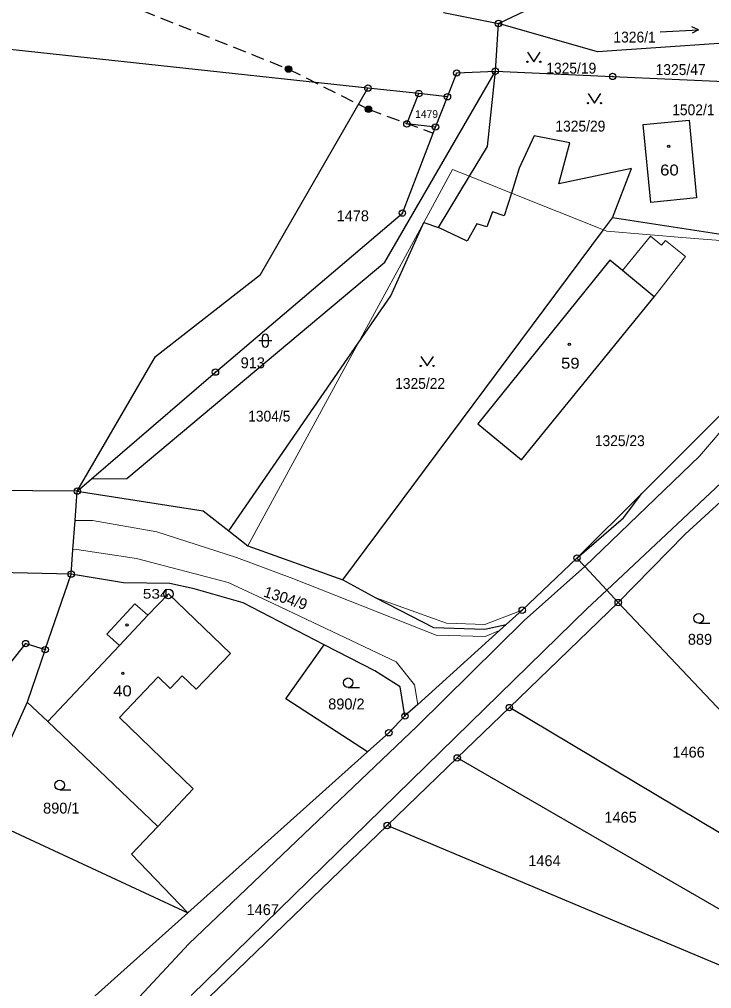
# Model space of a CAD drawing. Extents: x -872229 to -869198, y -1075981 to -1074329.
# Drawn here: x -871207 to -871098.8, y -1075369.5 to -1075218 of the extents above; entities that cross this region are included whole.
import ezdxf
from ezdxf.enums import TextEntityAlignment as Align

# ---------------------------------------------------------------- set-up
doc = ezdxf.new("R2010")
doc.units = 0
doc.header["$LTSCALE"] = 0.68
doc.linetypes.add('MEDIUM_DASHED', pattern=[4.5, 3, -1.5])
for name, color, linetype, lineweight in [('1', 7, 'Continuous', 25), ('3', 7, 'Continuous', 25), ('4', 7, 'Continuous', 13), ('5', 7, 'Continuous', 25), ('6', 7, 'Continuous', 25), ('8', 7, 'Continuous', 25)]:
    doc.layers.add(name, color=color, linetype=linetype, lineweight=lineweight)
doc.layers.add('2', color=7, linetype='Continuous')

msp = doc.modelspace()

# ---------------------------------------------------------------- linework, layer by layer
at = {"layer": '1'}
for p, q in [((-871144.59, -1075229.61), (-871152.53, -1075228.75)), ((-871083.47, -1075253.75), (-871114.29, -1075249)), ((-871197.94, -1075291.72), (-871195.74, -1075289.82)), ((-871156.43, -1075305.59), (-871151.31, -1075308.38)), ((-871113.42, -1075309.13), (-871130.43, -1075325.54)), ((-871202.96, -1075316.49), (-871205.8, -1075324.68)), ((-871130.43, -1075325.54), (-871138.58, -1075333.41)), ((-871149.52, -1075343.97), (-871178.79, -1075372.22)), ((-871078.37, -1075373.89), (-871149.52, -1075343.97))]:
    msp.add_line(p, q, dxfattribs=at)
for points in [[(-871152.53, -1075228.75), (-871324.15, -1075210.15), (-871498.95, -1075191.88), (-871564.6, -1075180.17), (-871590.36, -1075167.06), (-871608.79, -1075266.42)], [(-871140.73, -1075216.95), (-871132.14, -1075218.66), (-871123.91, -1075214.69)], [(-871140.11, -1075230.1), (-871138.66, -1075226.39), (-871132.62, -1075226.11), (-871132.14, -1075218.66)], [(-871093.1, -1075221.48), (-871116.67, -1075223.11), (-871132.14, -1075218.66)], [(-871195.74, -1075289.82), (-871190.23, -1075289.74), (-871149.91, -1075255.96), (-871132.62, -1075226.11)], [(-871141.5, -1075250.52), (-871136.68, -1075242.53), (-871133.87, -1075237.87), (-871132.62, -1075226.11)], [(-871132.62, -1075226.11), (-871114.29, -1075226.93), (-871095.65, -1075227.79), (-871094.24, -1075242.63), (-871087.01, -1075243.79), (-871083.47, -1075253.75), (-871081.37, -1075254)], [(-871197.94, -1075291.72), (-871185.72, -1075270.67), (-871169.32, -1075257.9), (-871152.53, -1075228.75)], [(-871141.97, -1075234.83), (-871146.44, -1075234.35), (-871144.59, -1075229.61)], [(-871141.97, -1075234.83), (-871140.11, -1075230.1), (-871144.59, -1075229.61)], [(-871195.74, -1075289.82), (-871176.36, -1075273.13), (-871147.15, -1075248.28), (-871142.34, -1075235.78), (-871141.97, -1075234.83)], [(-871114.29, -1075249), (-871111.33, -1075241.33), (-871122.72, -1075243.71), (-871120.98, -1075237.29), (-871126.58, -1075236.21), (-871128.88, -1075241.26), (-871130.08, -1075245.17), (-871131.22, -1075248.69), (-871133.07, -1075248.06), (-871133.96, -1075250.43), (-871135.52, -1075249.95), (-871137.04, -1075252.66), (-871141.5, -1075250.52)], [(-871174.28, -1075297.93), (-871154.05, -1075268.6), (-871148.96, -1075261.22), (-871143.79, -1075249.74), (-871141.5, -1075250.52)], [(-871156.43, -1075305.59), (-871115.7, -1075250.9), (-871114.29, -1075249)], [(-871119.87, -1075302.18), (-871112.61, -1075295.91), (-871109.75, -1075292.07), (-871095.22, -1075277.55), (-871091.41, -1075272.82)], [(-871197.94, -1075291.72), (-871226.01, -1075291.51), (-871257.41, -1075294.08), (-871286.96, -1075298.91), (-871317.28, -1075305.51), (-871377.38, -1075316.93)], [(-871198.89, -1075304.69), (-871198.62, -1075300.91), (-871198.28, -1075296.29), (-871197.94, -1075291.72)], [(-871197.94, -1075291.72), (-871178.28, -1075294.81), (-871174.28, -1075297.93)], [(-871096.84, -1075292.82), (-871102.97, -1075298.45), (-871113.42, -1075309.13)], [(-871174.28, -1075297.93), (-871171.28, -1075300.27), (-871156.43, -1075305.59)], [(-871119.87, -1075302.18), (-871128.42, -1075310.32), (-871130.92, -1075312.57)], [(-871113.42, -1075309.13), (-871115.21, -1075307.2), (-871118.65, -1075303.5), (-871119.87, -1075302.18)], [(-871198.89, -1075304.69), (-871226.19, -1075304.09), (-871258.51, -1075307.55), (-871284.79, -1075311.01), (-871308.94, -1075316.35)], [(-871243.8, -1075363.33), (-871206.01, -1075315.54), (-871202.96, -1075316.49), (-871198.89, -1075304.69)], [(-871159.38, -1075315.72), (-871172.04, -1075309.18), (-871179.69, -1075306.97), (-871183.47, -1075306.17), (-871190.75, -1075306.03), (-871198.89, -1075304.69)], [(-871151.31, -1075308.38), (-871142.29, -1075313.05), (-871134.29, -1075313.31), (-871130.92, -1075312.57)], [(-871073.44, -1075344.48), (-871095.32, -1075328.3), (-871113.42, -1075309.13)], [(-871130.92, -1075312.57), (-871131.97, -1075313.52), (-871144.74, -1075325.04), (-871146.74, -1075326.85)], [(-871152.59, -1075332.45), (-871165.34, -1075324.15), (-871159.38, -1075315.72)], [(-871146.74, -1075326.85), (-871147.48, -1075322.31), (-871151.47, -1075319.8), (-871159.38, -1075315.72)], [(-871205.8, -1075324.68), (-871208.57, -1075330.98), (-871218.91, -1075339.87), (-871180.67, -1075357.59)], [(-871205.8, -1075324.68), (-871202.55, -1075327.7), (-871185.37, -1075344.12), (-871189.49, -1075348.43), (-871180.67, -1075357.59)], [(-871074.84, -1075352.78), (-871079.33, -1075352.72), (-871094.35, -1075347.04), (-871130.43, -1075325.54)], [(-871146.74, -1075326.85), (-871149.26, -1075329.47), (-871152.59, -1075332.45), (-871180.67, -1075357.59), (-871200.62, -1075375.46)], [(-871077.5, -1075368.64), (-871138.58, -1075333.41), (-871149.52, -1075343.97)]]:
    msp.add_lwpolyline(points, dxfattribs=at)
for points in [[(-871101.2, -1075245.89), (-871108.3, -1075246.6), (-871109.5, -1075234.44), (-871102.34, -1075233.74)], [(-871114.73, -1075255.63), (-871135.35, -1075281.2), (-871128.52, -1075286.81), (-871107.81, -1075261.35), (-871112.73, -1075257.25)]]:
    msp.add_lwpolyline(points, close=True, dxfattribs=at)
at = {"layer": '3'}
for p, q in [((-871100.897, -1075219.631), (-871101.846, -1075220.183)), ((-871169.571, -1075268.211), (-871167.569, -1075268.211)), ((-871169.071, -1075267.711), (-871169.071, -1075268.712)), ((-871168.069, -1075268.712), (-871168.069, -1075267.711)), ((-871100.843, -1075312.36), (-871099.093, -1075312.36)), ((-871155.623, -1075322.42), (-871153.873, -1075322.42)), ((-871200.693, -1075338.4), (-871198.943, -1075338.4))]:
    msp.add_line(p, q, dxfattribs=at)
for points in [[(-871106.888, -1075219.945), (-871100.897, -1075219.631), (-871101.899, -1075219.181)], [(-871127.61, -1075223.129), (-871126.61, -1075224.63), (-871125.61, -1075223.129)], [(-871118.13, -1075229.609), (-871117.13, -1075231.11), (-871116.13, -1075229.609)], [(-871144.28, -1075270.669), (-871143.28, -1075272.17), (-871142.28, -1075270.669)]]:
    msp.add_lwpolyline(points, dxfattribs=at)
for centre, radius in [((-871127.61, -1075224.6295), 0.1), ((-871125.61, -1075224.6295), 0.1), ((-871118.13, -1075231.1095), 0.1), ((-871116.13, -1075231.1095), 0.1), ((-871144.28, -1075272.1695), 0.1), ((-871142.28, -1075272.1695), 0.1), ((-871100.8429, -1075311.6098), 0.75), ((-871155.6229, -1075321.6698), 0.75), ((-871200.6929, -1075337.6498), 0.75)]:
    msp.add_circle(centre, radius, dxfattribs=at)
for centre, start, end in [((-871168.57, -1075267.7109), 0, 180), ((-871168.57, -1075268.7109), 180, 359.98789)]:
    msp.add_arc(centre, 0.5, start, end, dxfattribs=at)
at = {"layer": '4'}
for p, q in [((-871143.79, -1075249.74), (-871139.3, -1075241.49)), ((-871130.08, -1075245.17), (-871115.7, -1075250.9)), ((-871154.05, -1075268.6), (-871143.79, -1075249.74)), ((-871112.73, -1075257.25), (-871108.4, -1075251.89)), ((-871108.4, -1075251.89), (-871106.66, -1075253.29)), ((-871102.8, -1075252.13), (-871083.47, -1075253.75)), ((-871107.81, -1075261.35), (-871102.92, -1075255.07)), ((-871171.28, -1075300.27), (-871154.05, -1075268.6)), ((-871100.71, -1075286.26), (-871088.11, -1075271.44)), ((-871118.65, -1075303.5), (-871100.71, -1075286.26)), ((-871115.21, -1075307.2), (-871096.49, -1075289.67)), ((-871119.87, -1075302.18), (-871109.75, -1075292.07)), ((-871198.28, -1075296.29), (-871195.57, -1075296.31)), ((-871195.57, -1075296.31), (-871185.5, -1075298.06)), ((-871185.5, -1075298.06), (-871173.09, -1075302.09)), ((-871198.62, -1075300.91), (-871198.04, -1075300.83)), ((-871198.04, -1075300.83), (-871188.7, -1075302.25)), ((-871188.7, -1075302.25), (-871174.37, -1075306)), ((-871173.09, -1075302.09), (-871164.26, -1075305.38)), ((-871118.65, -1075303.5), (-871128.14, -1075311.92)), ((-871174.37, -1075306), (-871168.13, -1075308.89)), ((-871164.26, -1075305.38), (-871141.89, -1075314.23)), ((-871118.25, -1075310.04), (-871115.21, -1075307.2)), ((-871186.94, -1075311.08), (-871183.69, -1075307.78)), ((-871183.69, -1075307.78), (-871174, -1075317.1)), ((-871168.13, -1075308.89), (-871148.13, -1075318.4)), ((-871151.31, -1075308.38), (-871140.23, -1075312.34)), ((-871193.35, -1075314.06), (-871188.96, -1075309.34)), ((-871188.96, -1075309.34), (-871186.94, -1075311.08)), ((-871180.16, -1075370.54), (-871118.25, -1075310.04)), ((-871134.25, -1075312.54), (-871128.42, -1075310.32)), ((-871191.36, -1075315.85), (-871186.94, -1075311.08)), ((-871128.14, -1075311.92), (-871144.78, -1075328.38)), ((-871140.23, -1075312.34), (-871134.25, -1075312.54)), ((-871134.21, -1075314.46), (-871131.97, -1075313.52)), ((-871193.35, -1075314.06), (-871191.36, -1075315.85)), ((-871141.89, -1075314.23), (-871134.21, -1075314.46)), ((-871202.55, -1075327.7), (-871191.36, -1075315.85)), ((-871191.36, -1075327.09), (-871185.32, -1075320.73)), ((-871185.32, -1075320.73), (-871183.41, -1075322.55)), ((-871191.36, -1075327.09), (-871179.85, -1075338.26)), ((-871185.37, -1075344.12), (-871179.85, -1075338.26))]:
    msp.add_line(p, q, dxfattribs=at)
for points in [[(-871139.3, -1075241.49), (-871136.68, -1075242.53), (-871130.08, -1075245.17)], [(-871115.7, -1075250.9), (-871115.22, -1075251.09), (-871102.8, -1075252.13)], [(-871106.66, -1075253.29), (-871106.05, -1075252.54), (-871102.92, -1075255.07)], [(-871183.41, -1075322.55), (-871181.54, -1075320.58), (-871179.36, -1075322.65), (-871174, -1075317.1)], [(-871148.13, -1075318.4), (-871145.25, -1075321.99), (-871144.74, -1075325.04)], [(-871144.78, -1075328.38), (-871161.44, -1075344.27), (-871180.53, -1075362.44), (-871193.17, -1075376.03)]]:
    msp.add_lwpolyline(points, dxfattribs=at)
at = {"layer": '5'}
for centre in [(-871105.5368, -1075237.8592), (-871121.0768, -1075268.7992), (-871190.1768, -1075312.6392), (-871190.8268, -1075320.1992)]:
    msp.add_circle(centre, 0.175, dxfattribs=at)
at = {"layer": '6', "linetype": 'MEDIUM_DASHED'}
for p, q in [((-871219.01, -1075204.11), (-871164.94, -1075225.78)), ((-871164.94, -1075225.78), (-871152.45, -1075232.06)), ((-871152.45, -1075232.06), (-871142.34, -1075235.78))]:
    msp.add_line(p, q, dxfattribs=at)
at = {"layer": '6'}
for centre, radius in [((-871164.9434, -1075225.7799), 0.5), ((-871164.9434, -1075225.7799), 0.4), ((-871164.9434, -1075225.7799), 0.3), ((-871164.9434, -1075225.7799), 0.2), ((-871164.9434, -1075225.7799), 0.1), ((-871152.4534, -1075232.0599), 0.5), ((-871152.4534, -1075232.0599), 0.4), ((-871152.4534, -1075232.0599), 0.3), ((-871152.4534, -1075232.0599), 0.2), ((-871152.4534, -1075232.0599), 0.1)]:
    msp.add_circle(centre, radius, dxfattribs=at)
at = {"layer": '8'}
for centre, radius in [((-871132.14, -1075218.6599), 0.5), ((-871132.14, -1075218.6599), 0.0303), ((-871138.66, -1075226.3899), 0.5), ((-871132.62, -1075226.1099), 0.5), ((-871138.66, -1075226.3899), 0.0303), ((-871132.62, -1075226.1099), 0.0303), ((-871114.29, -1075226.9299), 0.5), ((-871114.29, -1075226.9299), 0.0303), ((-871152.53, -1075228.7499), 0.5), ((-871152.53, -1075228.7499), 0.0303), ((-871144.59, -1075229.6099), 0.5), ((-871144.59, -1075229.6099), 0.0303), ((-871140.11, -1075230.0999), 0.5), ((-871140.11, -1075230.0999), 0.0303), ((-871146.44, -1075234.3499), 0.5), ((-871146.44, -1075234.3499), 0.0303), ((-871141.97, -1075234.8299), 0.5), ((-871141.97, -1075234.8299), 0.0303), ((-871147.15, -1075248.2799), 0.5), ((-871147.15, -1075248.2799), 0.0303), ((-871176.36, -1075273.1299), 0.5), ((-871176.36, -1075273.1299), 0.0303), ((-871197.94, -1075291.7199), 0.5), ((-871197.94, -1075291.7199), 0.0303), ((-871119.87, -1075302.1799), 0.5), ((-871119.87, -1075302.1799), 0.0303), ((-871198.89, -1075304.6899), 0.5), ((-871198.89, -1075304.6899), 0.0303), ((-871183.69, -1075307.7798), 0.75), ((-871183.69, -1075307.7798), 0.03), ((-871113.42, -1075309.1299), 0.5), ((-871113.42, -1075309.1299), 0.0303), ((-871128.42, -1075310.3199), 0.5), ((-871128.42, -1075310.3199), 0.0303), ((-871206.01, -1075315.5399), 0.5), ((-871206.01, -1075315.5399), 0.0303), ((-871202.96, -1075316.4899), 0.5), ((-871202.96, -1075316.4899), 0.0303), ((-871130.43, -1075325.5399), 0.5), ((-871130.43, -1075325.5399), 0.0303), ((-871146.74, -1075326.8499), 0.5), ((-871146.74, -1075326.8499), 0.0303), ((-871149.26, -1075329.4699), 0.5), ((-871149.26, -1075329.4699), 0.0303), ((-871138.58, -1075333.4099), 0.5), ((-871138.58, -1075333.4099), 0.0303), ((-871149.52, -1075343.9699), 0.5), ((-871149.52, -1075343.9699), 0.0303)]:
    msp.add_circle(centre, radius, dxfattribs=at)

# ---------------------------------------------------------------- texts
at = {"layer": '2'}
for s, width, p in [('1326/1', 0.95, (-871114.17, -1075221.63)), ('1325/19', 0.95, (-871124.66, -1075226.49)), ('1325/29', 0.95, (-871123.24, -1075235.54)), ('59', 1.15, (-871122.36, -1075272.59)), ('1325/22', 0.95, (-871148.28, -1075275.75)), ('1304/5', 0.95, (-871171.25, -1075280.86)), ('1325/23', 0.95, (-871117.08, -1075284.69)), ('40', 1.15, (-871192.34, -1075323.79))]:
    msp.add_text(s, height=1.7, dxfattribs=dict(at, width=width)).set_placement(p)
for s, width, p in [('1325/47', 0.95, (-871103.67, -1075226.71)), ('1502/1', 0.95, (-871101.679, -1075232.99)), ('60', 1.15, (-871105.42, -1075242.4))]:
    msp.add_text(s, height=1.7, dxfattribs=dict(at, width=width)).set_placement(p, align=Align.CENTER)
for s, height, p in [('1479', 1.2, (-871145.15, -1075233.4)), ('1478', 1.7, (-871157.43, -1075249.56)), ('913', 1.7, (-871172.42, -1075272.52)), ('889', 1.7, (-871102.54, -1075315.73)), ('890/2', 1.7, (-871158.74, -1075325.83)), ('1466', 1.7, (-871104.95, -1075333.35)), ('890/1', 1.7, (-871203.29, -1075342.1)), ('1465', 1.7, (-871115.58, -1075343.53)), ('1464', 1.7, (-871127.48, -1075350.32)), ('1467', 1.7, (-871171.5, -1075357.96))]:
    msp.add_text(s, height=height, dxfattribs=at).set_placement(p)
msp.add_text('1304/9', height=1.7, rotation=342, dxfattribs=at).set_placement((-871168.962, -1075308.168))
at = {"layer": '8', "width": 1.2}
msp.add_text('534', height=1.5, dxfattribs=at).set_placement((-871183.69, -1075308.53), align=Align.RIGHT)

doc.saveas('drawing.dxf')
